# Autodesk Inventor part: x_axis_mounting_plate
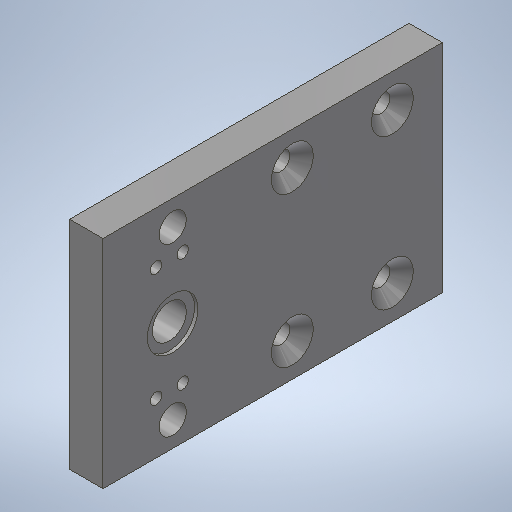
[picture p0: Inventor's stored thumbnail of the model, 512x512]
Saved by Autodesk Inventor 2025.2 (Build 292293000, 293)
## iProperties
Created: 2025-04
Part Number: x_axis_mounting_plate
Material: 1.0037 S235JR
Document SubType Name: Modeling
Designer: BennF
Density: 7.85 g/cm^3
Appearance: Stahl
Author: BennF
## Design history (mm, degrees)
sketch "Sketch2"
  geometry: L1 (-50.9, 32.5)-(50.9, 32.5); L2 (50.9, 32.5)-(50.9, -32.5); L3 (50.9, -32.5)-(-50.9, -32.5); L4 (-50.9, -32.5)-(-50.9, 32.5); 3 further points
  constraints: 8 end point, 2 midpoint, 2 parallel, 1 horizontal, 1 horizontal alignment, 1 perpendicular, 1 vertical alignment
  dimensions: "d0" = 65 distance of L3.end L1.start; "d1" = 101.8 distance of L1.start L1.end
extrude "Extrusion1" new body sketch "Sketch2" distance "d2" = 10; taper "d3" = 0 deg
sketch "Sketch3"
  geometry: L1 (-22.5, 35.9)-(22.5, 35.9); L2 (32.5, 50.9)-(-32.5, 50.9) reference; 4 further points
  constraints: 3 vertical alignment, 2 end point, 2 horizontal alignment, 2 midpoint
  dimensions: "d11" = 45 distance of L1.end L1.start (computed from d0); "d25" = 15 distance from line of L2 L1.start; "d36" = 30 distance of point (-22.5, 5.9) L1.start
hole "Hole1" sketch "Sketch3" at (-22.5, 35.9), (22.5, 35.9), (-22.5, 5.9), (22.5, 5.9) diameter "d4" = 5.5; stored, may be unused: countersink angle "d8" = 90 deg, drill point angle "d10" = 118 deg; dims "d5" = 6, "d6" = 12.5, "d7" = 2, "d9" = 8
sketch "Sketch4"
  geometry: L1 (-25, -30)-(25, -30); L2 (-32.5, -50.9)-(32.5, -50.9) reference; C1 r 4.075 at (-25, -30); C2 r 4.075 at (25, -30); 2 further points
  constraints: 2 centre point, 2 end point, 2 midpoint, 1 equal radius, 1 horizontal alignment, 1 vertical alignment
  dimensions: "d12" = 50 distance of L1.start L1.end; "d13" = 8.15 diameter of C1; "d21" = -20.9 distance between parallel lines of L1 L2
extrude "Extrusion2" cut sketch "Sketch4" stored distance "d14" = 7; taper "d15" = 0 deg
workplane "Work Plane1"
sketch "Sketch5"
  geometry: L1 (-10, -45)-(-10, 20) reference; L2 (-10, -4.925)-(-9, -4.925); L3 (-9, -4.925)-(-9, -7.425); L4 (-9, -7.425)-(0, -7.425); L5 (0, -45)-(0, 20) reference; L6 (0, -12.5)-(-10, -12.5)
  constraints: 8 end point, 3 perpendicular, 2 point on line, 1 midpoint
  dimensions: "d16" = 10.15 diameter of L4 L6; "d17" = 15.15 diameter of L2 L6; "d24" = 1 distance of L2.start L2.end
revolve "Revolution1" sketch "Sketch5" stored, may be unused: angle "d19" = 90 deg
sketch "Sketch6"
  geometry: L1 (17, -27)-(17, -35); C1 r 4.075 at (25, -30) reference; 1 further point
  constraints: 2 end point, 1 vertical, 1 vertical alignment
  dimensions: "d33" = 8 distance from line of L1 C1.centre; "d34" = 8 distance of L1.start L1.end; "d35" = 3 vertical distance of C1.centre L1.start (computed from d34)
hole "Hole2" sketch "Sketch6" at (17, -27), (17, -35) diameter "d26" = 3.4; stored, may be unused: countersink angle "d30" = 90 deg, drill point angle "d32" = 118 deg; dims "d27" = 10 (= d2), "d28" = 7.5, "d29" = 2, "d31" = 8
workplane "Work Plane2"
mirror "Mirror1"
body "Solid1"
other parameters: "d22" = -20.9
